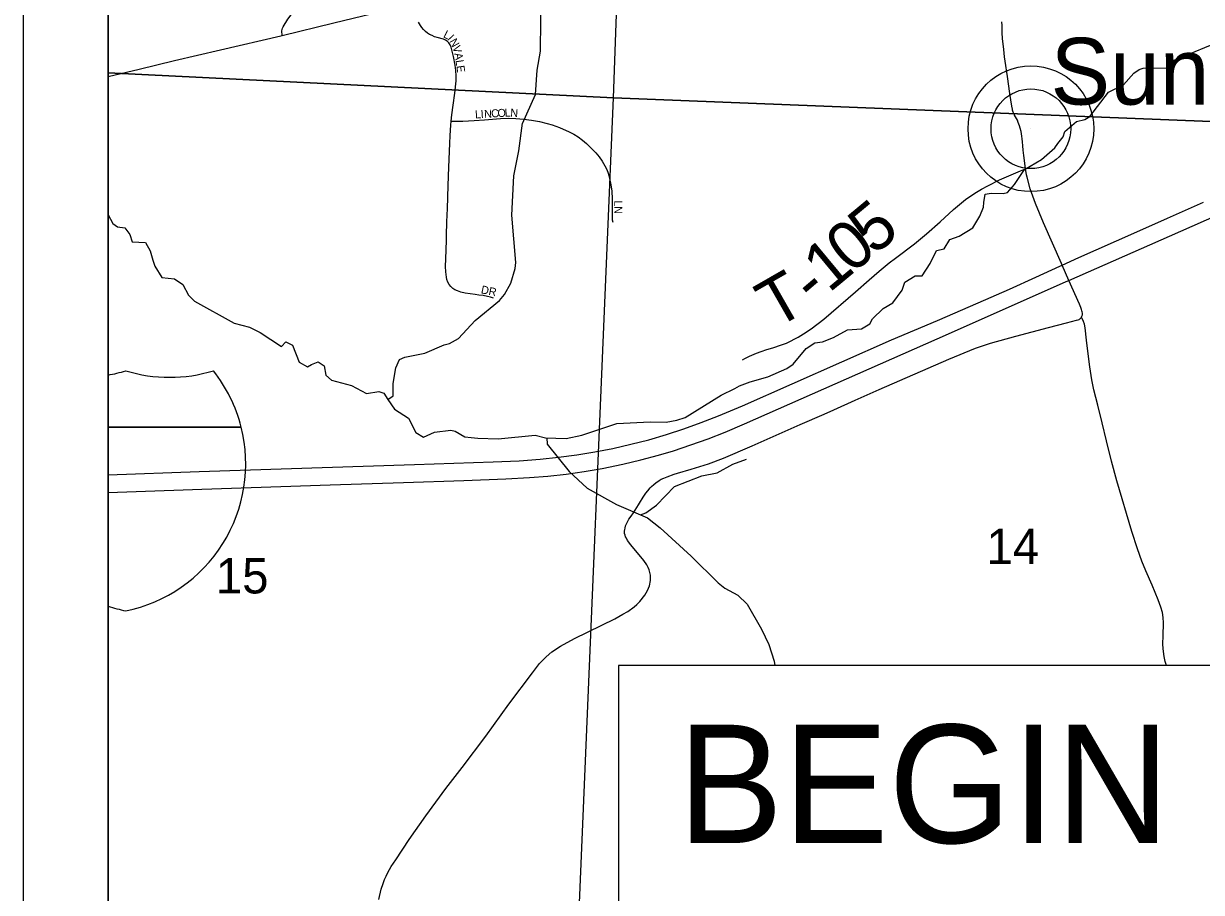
# Model space of a CAD drawing. Extents: x 0 to 34, y 0 to 22.
# Drawn here: x 23.917 to 25.311, y 15.353 to 16.381 of the extents above; entities that cross this region are included whole.
import ezdxf

# ---------------------------------------------------------------- set-up
doc = ezdxf.new("R2010")
doc.units = 0
for name, color, linetype in [('GM_X_Adjacent_County', 7, 'Continuous'), ('GM_X_County', 7, 'Continuous'), ('GM_X_County_Road', 7, 'Continuous'), ('GM_X_Interstate_Location', 7, 'Continuous'), ('GM_X_Interstate_Route', 7, 'Continuous'), ('GM_X_Interstate_Shield', 7, 'Continuous'), ('GM_X_Minor_River', 7, 'Continuous'), ('GM_X_Section', 7, 'Continuous'), ('GM_X_Section_Text', 7, 'Continuous'), ('GM_X_Township', 7, 'Continuous'), ('GM_X_Township_Road', 7, 'Continuous'), ('GM_X_Township_Road_Text', 7, 'Continuous'), ('GM_X_Township_Subdivision', 7, 'Continuous'), ('GM_X_Township_Subdivision_Text', 7, 'Continuous'), ('GM_X_Unincorporated', 7, 'Continuous'), ('GM_X_Unincorporated_Location', 7, 'Continuous'), ('GM_X_Unincorporated_Text', 7, 'Continuous'), ('GM_X_US_Route', 7, 'Continuous'), ('SH_Data', 7, 'Continuous'), ('SH_Text', 7, 'Continuous')]:
    doc.layers.add(name, color=color, linetype=linetype)

msp = doc.modelspace()

# ---------------------------------------------------------------- linework, layer by layer
at = {"layer": 'GM_X_Adjacent_County'}
msp.add_lwpolyline([(28.7526, 20.9), (24.0167, 20.9), (24.0167, 14.1), (28.5181, 14.1)], dxfattribs=at)
at = {"layer": 'GM_X_County'}
msp.add_lwpolyline([(28.7526, 20.9), (24.0167, 20.9), (24.0167, 14.1), (28.5181, 14.1)], dxfattribs=at)
at = {"layer": 'GM_X_County_Road'}
for points in [[(25.0894, 16.273), (25.0887, 16.2744), (25.088, 16.276), (25.0873, 16.2785), (25.087, 16.2795), (25.0863, 16.2832), (25.084, 16.2983), (25.0811, 16.3184), (25.0786, 16.3363), (25.0778, 16.3417), (25.0767, 16.3503), (25.0761, 16.3571), (25.0755, 16.3628), (25.0751, 16.3704), (25.0748, 16.3788), (25.0747, 16.3831)], [(25.1027, 16.209), (25.1017, 16.2155), (25.1005, 16.2249), (25.0998, 16.2312), (25.0994, 16.236), (25.099, 16.2409), (25.0986, 16.2443), (25.0983, 16.2478), (25.0978, 16.2505), (25.0973, 16.2532), (25.0963, 16.2571), (25.0955, 16.2597), (25.094, 16.2639), (25.093, 16.2664), (25.0918, 16.2687), (25.0907, 16.2707), (25.0896, 16.2726), (25.0894, 16.273)], [(25.1687, 16.0332), (25.1693, 16.0345), (25.1697, 16.0354), (25.1698, 16.0361), (25.1699, 16.0374), (25.1698, 16.0382), (25.1696, 16.0396), (25.1692, 16.041), (25.1687, 16.0426), (25.1679, 16.0449), (25.1665, 16.0486), (25.154, 16.0769), (25.146, 16.0951), (25.1452, 16.0969), (25.1238, 16.1451), (25.1142, 16.1679), (25.1081, 16.1854), (25.1045, 16.1992), (25.1038, 16.202), (25.1033, 16.2045), (25.1027, 16.209)], [(24.6457, 15.8132), (24.65, 15.8203), (24.6533, 15.8252), (24.6554, 15.8278), (24.6584, 15.8314), (24.66, 15.8331), (24.6625, 15.8354), (24.6652, 15.8374), (24.669, 15.84), (24.6715, 15.8415), (24.6743, 15.8429), (24.6783, 15.8446), (24.6866, 15.8474), (24.6907, 15.8486), (24.7067, 15.8534), (24.7275, 15.8599), (24.745, 15.8665), (24.7792, 15.8812), (24.836, 15.9063), (24.8642, 15.9187), (24.8756, 15.9237), (24.901, 15.9352), (24.9294, 15.9476), (25.0119, 15.9837), (25.0435, 15.9966), (25.0611, 16.0025), (25.0909, 16.0111), (25.1298, 16.0213), (25.1509, 16.0265), (25.163, 16.0297), (25.1648, 16.0303), (25.1659, 16.0308), (25.1668, 16.0313), (25.1675, 16.0318), (25.1682, 16.0325), (25.1687, 16.0332)], [(25.1748, 16.0062), (25.1732, 16.0209), (25.1723, 16.0251), (25.1711, 16.0281), (25.1687, 16.0332)], [(25.2693, 15.621), (25.268, 15.6258), (25.2667, 15.6317), (25.2654, 15.6408), (25.265, 15.6469), (25.2653, 15.6561), (25.2658, 15.6716), (25.2655, 15.6778), (25.2645, 15.684), (25.2628, 15.6901), (25.2597, 15.6989), (25.2525, 15.7161), (25.2451, 15.7331), (25.2404, 15.7445), (25.2351, 15.7591), (25.2283, 15.7796), (25.2108, 15.8398), (25.2045, 15.863), (25.1983, 15.8871), (25.1933, 15.9082), (25.188, 15.9292), (25.1836, 15.9473), (25.1812, 15.9594), (25.1788, 15.9747), (25.1756, 15.9993), (25.1748, 16.0062)], [(24.3371, 15.3442), (24.34, 15.3563), (24.3422, 15.3632), (24.344, 15.3679), (24.3457, 15.3718), (24.3478, 15.3763), (24.3519, 15.3831), (24.3571, 15.3913), (24.3732, 15.4152), (24.3928, 15.4432), (24.4166, 15.4757), (24.4356, 15.5003), (24.4637, 15.5375), (24.4911, 15.5753), (24.5191, 15.6126), (24.5275, 15.6233), (24.5324, 15.6285), (24.5351, 15.6313), (24.5421, 15.6372), (24.5523, 15.6441), (24.5686, 15.6529), (24.6165, 15.6765), (24.626, 15.6818), (24.6318, 15.6852), (24.6394, 15.6906), (24.6426, 15.6935), (24.6462, 15.697), (24.652, 15.7044), (24.6551, 15.7098), (24.6575, 15.7156), (24.6587, 15.7218), (24.6587, 15.7282), (24.6573, 15.7344), (24.6561, 15.7373), (24.6545, 15.7401), (24.6509, 15.7452), (24.6373, 15.7615), (24.6351, 15.7642), (24.6332, 15.767), (24.6316, 15.7692), (24.6302, 15.7718), (24.6293, 15.7734), (24.6286, 15.7754), (24.6281, 15.7772), (24.6278, 15.7789), (24.628, 15.7802), (24.6282, 15.7821), (24.6286, 15.7838), (24.6293, 15.7865), (24.6303, 15.7889), (24.6315, 15.7912), (24.6332, 15.7942), (24.6357, 15.7979), (24.6385, 15.8018), (24.6446, 15.8114), (24.6457, 15.8132)]]:
    msp.add_lwpolyline(points, dxfattribs=at)
at = {"layer": 'GM_X_Interstate_Route'}
for points in [[(24.0167, 15.826), (24.0499, 15.8272), (24.1275, 15.83), (24.2796, 15.8349), (24.3665, 15.8377), (24.4379, 15.8402), (24.4876, 15.8419), (24.5155, 15.8435), (24.5371, 15.8453), (24.5587, 15.8477), (24.5802, 15.8507), (24.6016, 15.8544), (24.6259, 15.8594), (24.6471, 15.8644), (24.6681, 15.87), (24.6859, 15.8753), (24.7065, 15.8821), (24.7269, 15.8895), (24.7471, 15.8974), (24.77, 15.9071), (25.0115, 16.0138), (25.1507, 16.0755), (25.154, 16.0769), (25.2729, 16.1292), (25.4007, 16.1858)], [(24.0167, 15.8468), (24.1246, 15.8506), (24.3792, 15.8589), (24.4723, 15.862), (24.5034, 15.8635), (24.5282, 15.8653), (24.5499, 15.8675), (24.5715, 15.8704), (24.5929, 15.8739), (24.6143, 15.8781), (24.6356, 15.8829), (24.6566, 15.8884), (24.6776, 15.8944), (24.6983, 15.9012), (24.7187, 15.9086), (24.739, 15.9165), (24.7677, 15.9286), (24.9439, 16.0064), (24.9982, 16.0294), (25.0466, 16.0504), (25.0836, 16.0666), (25.1148, 16.0806), (25.143, 16.0937), (25.146, 16.0951), (25.1655, 16.104), (25.2308, 16.133), (25.2706, 16.1507), (25.3132, 16.1695)]]:
    msp.add_lwpolyline(points, dxfattribs=at)
at = {"layer": 'GM_X_Interstate_Shield'}
for p, q in [((24.0167, 15.9649), (24.0167, 15.9034)), ((24.0167, 15.9034), (24.1742, 15.9034)), ((24.0167, 15.9034), (24.1742, 15.9034)), ((24.1742, 15.9034), (24.0167, 15.9034)), ((24.0167, 15.9034), (24.0167, 15.6915))]:
    msp.add_line(p, q, dxfattribs=at)
for centre, start, end in [((23.9857, 16.1398), 280.0359, 286.9909), ((24.0895, 16.1398), 253.0091, 286.9909), ((24.0021, 15.8598), 14.1934, 38.331), ((24.0021, 15.8598), 281.537, 14.1934), ((24.0731, 15.8598), 251.4607, 258.463)]:
    msp.add_arc(centre, 0.1776, start, end, dxfattribs=at)
at = {"layer": 'GM_X_Minor_River'}
for points in [[(24.5071, 16.2625), (24.5224, 16.2968), (24.5245, 16.3256), (24.5285, 16.3484), (24.5287, 16.3844), (24.5287, 16.4334), (24.5302, 16.4425), (24.5357, 16.4565), (24.5406, 16.4623), (24.5504, 16.4673), (24.566, 16.4696), (24.614, 16.4775), (24.6223, 16.4806), (24.6302, 16.4852), (24.6378, 16.4921), (24.6517, 16.499), (24.684, 16.4947), (24.6953, 16.4993), (24.7055, 16.5035)], [(24.892, 16.0184), (24.9083, 16.0197), (24.9181, 16.0254), (24.9215, 16.0315), (24.9339, 16.0437), (24.9456, 16.0503), (24.9565, 16.0655), (24.9598, 16.075), (24.9719, 16.0823), (24.9802, 16.0823), (24.9896, 16.0968), (24.9971, 16.1124), (25.0062, 16.1144), (25.0129, 16.1254), (25.0242, 16.1293), (25.0401, 16.1392), (25.0483, 16.153), (25.0528, 16.1636), (25.0531, 16.1693), (25.0546, 16.1788), (25.0618, 16.1803), (25.0762, 16.1797), (25.0811, 16.1809), (25.0897, 16.1904), (25.1014, 16.2083), (25.1213, 16.2202), (25.1372, 16.2339), (25.1409, 16.2389), (25.1473, 16.2469), (25.1492, 16.253), (25.1627, 16.2648), (25.1729, 16.2675), (25.1786, 16.271), (25.2007, 16.2996), (25.2185, 16.3084), (25.2309, 16.3221), (25.2369, 16.3264), (25.2418, 16.3283), (25.2721, 16.3285), (25.2785, 16.3376), (25.3397, 16.363)], [(24.348, 15.936), (24.354, 15.9402), (24.3543, 15.955), (24.3572, 15.9733), (24.3617, 15.9832), (24.3681, 15.9862), (24.3915, 15.9906), (24.4146, 16.0006), (24.4206, 16.0021), (24.4316, 16.0083), (24.4511, 16.0293), (24.4801, 16.0533), (24.4857, 16.0602), (24.4932, 16.0735), (24.4984, 16.091), (24.4995, 16.0982), (24.4946, 16.154), (24.4969, 16.2006), (24.5028, 16.2303), (24.5071, 16.2629)], [(24.0167, 16.1544), (24.0224, 16.1441), (24.0277, 16.1403), (24.0364, 16.1392), (24.0425, 16.1313), (24.0452, 16.1226), (24.0608, 16.1219), (24.0665, 16.1121), (24.0696, 16.1007), (24.072, 16.0936), (24.0804, 16.0803), (24.0955, 16.0789), (24.105, 16.0721), (24.1119, 16.0593), (24.1188, 16.0525), (24.1659, 16.0263), (24.1842, 16.0215), (24.1967, 16.0151), (24.2218, 15.9986), (24.2271, 16.0043), (24.235, 16.0002), (24.2428, 15.9801), (24.2526, 15.9745), (24.2575, 15.9772), (24.2655, 15.9806), (24.2723, 15.9757), (24.2743, 15.9648), (24.2811, 15.9587), (24.3047, 15.9524), (24.3225, 15.9431), (24.3373, 15.9454), (24.343, 15.9436), (24.348, 15.936), (24.3556, 15.9247), (24.3723, 15.9138), (24.3808, 15.8968), (24.3899, 15.8912), (24.4031, 15.8973), (24.4224, 15.8997), (24.4274, 15.8986), (24.4388, 15.8919), (24.4464, 15.8908), (24.4543, 15.8901), (24.4782, 15.8895), (24.5221, 15.8939), (24.5346, 15.8906), (24.5588, 15.8896), (24.5774, 15.8939), (24.6189, 15.9074), (24.6583, 15.9096), (24.6773, 15.9093), (24.6897, 15.9113), (24.6999, 15.9148), (24.7422, 15.9412), (24.7584, 15.9489), (24.7641, 15.952), (24.7765, 15.957), (24.7977, 15.9628), (24.82, 15.9725), (24.8275, 15.9778), (24.8429, 15.9965), (24.8531, 16.003), (24.8622, 16.0042), (24.8754, 16.0092), (24.892, 16.0184)], [(24.5359, 15.8905), (24.5365, 15.883), (24.5625, 15.8509), (24.5839, 15.831), (24.6184, 15.8118), (24.6553, 15.7958), (24.6701, 15.7841), (24.7067, 15.7506), (24.7387, 15.7189), (24.7467, 15.7125), (24.7619, 15.7043), (24.773, 15.6937), (24.7902, 15.6642), (24.7987, 15.6461), (24.8049, 15.6264), (24.8059, 15.621)], [(24.647, 15.7994), (24.653, 15.8018), (24.6658, 15.811), (24.6872, 15.8328), (24.7193, 15.8455), (24.7375, 15.849), (24.756, 15.8594), (24.7722, 15.8652)]]:
    msp.add_lwpolyline(points, dxfattribs=at)
at = {"layer": 'GM_X_Section'}
for p, q in [((24.0167, 17.3235), (24.0167, 16.3224)), ((24.0167, 16.3224), (24.0167, 15.3189))]:
    msp.add_line(p, q, dxfattribs=at)
for points in [[(24.0167, 16.3224), (24.6148, 16.293), (24.6507, 17.2941), (24.0167, 17.3235)], [(24.0167, 15.3189), (24.5727, 15.2931), (24.6148, 16.293), (24.0167, 16.3224)], [(24.6207, 15.2914), (24.5727, 15.2931), (24.6148, 16.293), (25.601, 16.254), (25.5786, 15.621)]]:
    msp.add_lwpolyline(points, dxfattribs=at)
msp.add_lwpolyline([(24.6507, 17.2941), (25.6316, 17.2576), (25.601, 16.254), (24.6148, 16.293)], close=True, dxfattribs=at)
at = {"layer": 'GM_X_Township'}
msp.add_lwpolyline([(24.0167, 18.4402), (24.0167, 14.1), (28.5181, 14.1)], dxfattribs=at)
at = {"layer": 'GM_X_Township_Road'}
for points in [[(24.2226, 16.3669), (24.2225, 16.3723), (24.2227, 16.3739), (24.2232, 16.3755), (24.2239, 16.377), (24.2296, 16.386), (24.237, 16.3959), (24.2409, 16.4003), (24.2435, 16.4026), (24.2469, 16.4051), (24.2493, 16.4069)], [(25.0172, 16.1607), (25.0196, 16.1628), (25.0317, 16.1725), (25.0368, 16.1763), (25.0444, 16.1812), (25.0506, 16.1849), (25.0578, 16.189), (25.0716, 16.1959), (25.0967, 16.2067), (25.1027, 16.209)], [(24.9176, 16.0776), (24.9294, 16.088), (24.9413, 16.0978), (24.9487, 16.1034), (24.971, 16.1201), (24.9854, 16.1319), (25.0015, 16.1463), (25.0172, 16.1607)], [(24.7676, 15.9829), (24.7702, 15.9846), (24.7757, 15.9874), (24.7843, 15.9909), (24.7897, 15.9929), (24.7962, 15.9952), (24.8036, 15.9972), (24.8138, 16.0005), (24.8196, 16.0028), (24.8252, 16.0052), (24.8289, 16.0072), (24.8334, 16.0096), (24.8399, 16.0136), (24.849, 16.0197), (24.8639, 16.031), (24.9014, 16.0635), (24.9176, 16.0776)]]:
    msp.add_lwpolyline(points, dxfattribs=at)
at = {"layer": 'GM_X_Township_Subdivision'}
for points in [[(24.4228, 16.2655), (24.4236, 16.2729), (24.4253, 16.2843), (24.4272, 16.2986), (24.4285, 16.313), (24.4287, 16.3192), (24.4283, 16.3254), (24.4275, 16.3316), (24.4255, 16.342), (24.4244, 16.3468), (24.4226, 16.3528), (24.4214, 16.3556), (24.4199, 16.3579), (24.4182, 16.3599), (24.416, 16.3614), (24.4138, 16.3623), (24.4061, 16.3643), (24.4031, 16.3653), (24.4002, 16.3666), (24.3973, 16.368), (24.3947, 16.3696), (24.3922, 16.3715), (24.3901, 16.3737), (24.3882, 16.3762), (24.3865, 16.3788), (24.3843, 16.3826)], [(24.4181, 16.1547), (24.4184, 16.1615), (24.4193, 16.1893), (24.4201, 16.211), (24.421, 16.239), (24.4214, 16.2483), (24.4222, 16.2606), (24.4228, 16.2655)], [(24.4228, 16.2655), (24.4275, 16.2655), (24.4367, 16.2655), (24.45, 16.2661), (24.4624, 16.2669), (24.481, 16.2684), (24.4902, 16.2688), (24.4995, 16.2685), (24.5088, 16.2677), (24.518, 16.2664), (24.5273, 16.2648), (24.5364, 16.2628), (24.5423, 16.261), (24.551, 16.2578), (24.5624, 16.2528), (24.5679, 16.25), (24.5732, 16.2467), (24.5782, 16.243), (24.5829, 16.2389), (24.5897, 16.2324), (24.5939, 16.2278), (24.5979, 16.223), (24.6015, 16.218), (24.6048, 16.2127), (24.6067, 16.2088), (24.6083, 16.2051), (24.6095, 16.2012), (24.6114, 16.1921), (24.6128, 16.1829), (24.6134, 16.1732), (24.6135, 16.1638), (24.6132, 16.1549), (24.6132, 16.1517), (24.6135, 16.1487), (24.6142, 16.1459)], [(24.473, 16.056), (24.4695, 16.0571), (24.4657, 16.058), (24.4605, 16.059), (24.4556, 16.0596), (24.451, 16.0602), (24.4454, 16.0611), (24.4393, 16.0619), (24.4343, 16.063), (24.4301, 16.0644), (24.4273, 16.0656), (24.4248, 16.0672), (24.4222, 16.0697), (24.4203, 16.0721), (24.4188, 16.0749), (24.4178, 16.0778), (24.4171, 16.0808), (24.4163, 16.087), (24.4161, 16.0932), (24.4163, 16.1025), (24.4171, 16.1243), (24.4171, 16.1305), (24.4178, 16.146), (24.4181, 16.1547)]]:
    msp.add_lwpolyline(points, dxfattribs=at)
at = {"layer": 'GM_X_Unincorporated'}
for radius in [0.0744, 0.0472]:
    msp.add_circle((25.1089, 16.2564), radius, dxfattribs=at)
at = {"layer": 'GM_X_Unincorporated_Location'}
msp.add_line((25.1089, 16.2564), (25.1089, 16.2564), dxfattribs=at)
at = {"layer": 'GM_X_US_Route'}
for points in [[(24.2226, 16.3669), (24.2838, 16.3816), (24.351, 16.3978), (24.3778, 16.4043), (24.3852, 16.4062), (24.4196, 16.4147)], [(24.0167, 16.3182), (24.0533, 16.3268), (24.0955, 16.337), (24.1499, 16.3499), (24.221, 16.3665), (24.2226, 16.3669)]]:
    msp.add_lwpolyline(points, dxfattribs=at)
at = {"layer": 'SH_Data'}
for points in [[(23.9167, 21), (30.9167, 21), (30.9167, 14), (23.9167, 14)], [(24.0167, 20.9), (30.8167, 20.9), (30.8167, 14.1), (24.0167, 14.1)]]:
    msp.add_lwpolyline(points, close=True, dxfattribs=at)
at = {"layer": 'SH_Text'}
msp.add_lwpolyline([(24.6207, 15.131), (26.3766, 15.131), (26.3766, 15.621), (24.6207, 15.621)], close=True, dxfattribs=at)

# ---------------------------------------------------------------- texts
at = {"layer": 'GM_X_Interstate_Location'}
for s in ['.', '-', ',']:
    msp.add_text(s, height=0.000189, dxfattribs=at).set_placement((24.0376, 15.8278))
at = {"layer": 'GM_X_Section_Text'}
for s, p in [('14', (25.0564, 15.7412)), ('15', (24.1443, 15.7064))]:
    msp.add_text(s, height=0.04186, rotation=0, dxfattribs=at).set_placement(p)
at = {"layer": 'GM_X_Township_Road_Text'}
for s, rotation, p in [('5', 39.7067, (24.9233, 16.1057)), ('0', 39.6884, (24.8965, 16.0835)), ('1', 39.6529, (24.8698, 16.0613)), ('T', 29.8088, (24.8061, 16.0187)), ('-', 40.4954, (24.8524, 16.0464))]:
    msp.add_text(s, height=0.0568, rotation=rotation, dxfattribs=at).set_placement(p)
at = {"layer": 'GM_X_Township_Subdivision_Text'}
for s, rotation, p in [('L', 332.5673, (24.4127, 16.3651)), ('I', 312.6501, (24.4179, 16.3626)), ('N', 299.1756, (24.4204, 16.36)), ('V', 286.7411, (24.4242, 16.3532)), ('A', 279.5953, (24.4265, 16.3455)), ('L', 278.3889, (24.4279, 16.3373)), ('E', 278.4264, (24.4289, 16.3307)), ('L', 3.6087, (24.4513, 16.2685)), ('I', 3.6249, (24.458, 16.2689)), ('N', 3.6091, (24.4621, 16.2691)), ('C', 3.6158, (24.4704, 16.2697)), ('O', 3.6255, (24.4779, 16.2701)), ('L', 0.683, (24.4861, 16.2707)), ('N', 356.7414, (24.4926, 16.2707)), ('LN', 270, (24.6157, 16.1717)), ('DR', 348.1171, (24.4575, 16.0618))]:
    msp.add_text(s, height=0.00947, rotation=rotation, dxfattribs=at).set_placement(p)
at = {"layer": 'GM_X_Unincorporated_Text'}
msp.add_text('Sundale', height=0.07898, rotation=0, dxfattribs=at).set_placement((25.1322, 16.285))
at = {"layer": 'SH_Text'}
msp.add_text('BEGIN PROJECT', height=0.14, dxfattribs=at).set_placement((24.6907, 15.411))

doc.saveas('drawing.dxf')
